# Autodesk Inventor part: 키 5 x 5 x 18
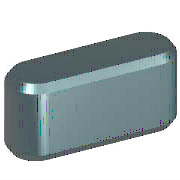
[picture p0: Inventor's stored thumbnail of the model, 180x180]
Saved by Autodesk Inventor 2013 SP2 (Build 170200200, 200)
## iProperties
IsCustomPart: 1
Created: 2012-02
Part Number: 키 5 x 5 x 18
Material: 강철, 연강
Description: 키 및 해당 키홈
Document SubType Name: Modeling
Standard: KS B 1311
Designer: mduedu
Standards Organization: KS
Language: ko-KR
Size Designation: 5 x 5 x 18
Categories: <MemberInstance><Categories><Category DisplayName="샤프트 부품" InternalName="7f7aeb1f-a693-4053-b835-cee3144e0d98" Mnemonic="SHFT"><Category DisplayName="키" Interna
Density: 1 g/cm^3
Author: mduedu
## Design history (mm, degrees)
workplane "Work Plane1"
workplane "Work Plane2"
sketch "스케치1"
  geometry: L1 (2.5, 2.5)-(15.5, 2.5); L2 (15.5, -2.5)-(2.5, -2.5); L3 (0, 9.4)-(0, -7.4) reference; L4 (-5, 0)-(30, 0) reference; L5 (18, 0)-(18, 7); A1 r 2.5 centre (2.5, 0) between (2.5, 2.5) and (2.5, -2.5); A2 r 2.5 centre (15.5, 0) between (15.5, -2.5) and (15.5, 2.5)
  constraints: 6 end point, 5 point on circle, 4 tangent, 3 point on line, 2 centre point, 1 horizontal, 1 parallel, 1 perpendicular
  dimensions: "d0" = 2.5 radius of A1 (= 0.5 x PB); "d13" = 2.5 radius of A2 (= 0.5 x PB); "d14" = 18 distance between parallel lines of L5 L3 (= NLG)
extrude "본체1" new body sketch "스케치1" taper "d3" = 0 deg; stored distance "d4" = 10
workplane "Work Plane3"
body "Solid1"
chamfer "모따기1" distance "d8" = 0.4 (= PHH); stored, may be unused: second distance "d9" = 0.4 (= PHH), angle "d15" = 45 deg
other parameters: "d1" = -3 (= -PNT), "d2" = 2 (= PH - PNT), "NLG" = 18 [user parameter; used in 3 equation terms], "PB" = 5 [user parameter; used in 2 equation terms], "PNT" = 3 [user parameter; used in 2 equation terms], "PH" = 5 [user parameter; used in 1 equation term], "PHH" = 0.4 [user parameter; used in 2 equation terms], "d10" = 0, "d16" = 0, "d17" = 0, "d18" = 0, "WDMIN" = 12 [user parameter], "PLB2" = 18 (= NLG) [user parameter], "WDMAX" = 17 [user parameter], "PLB1" = 18 (= NLG) [user parameter], "RR" = 0.16 [user parameter], "PUEB" = 2.3 [user parameter]
